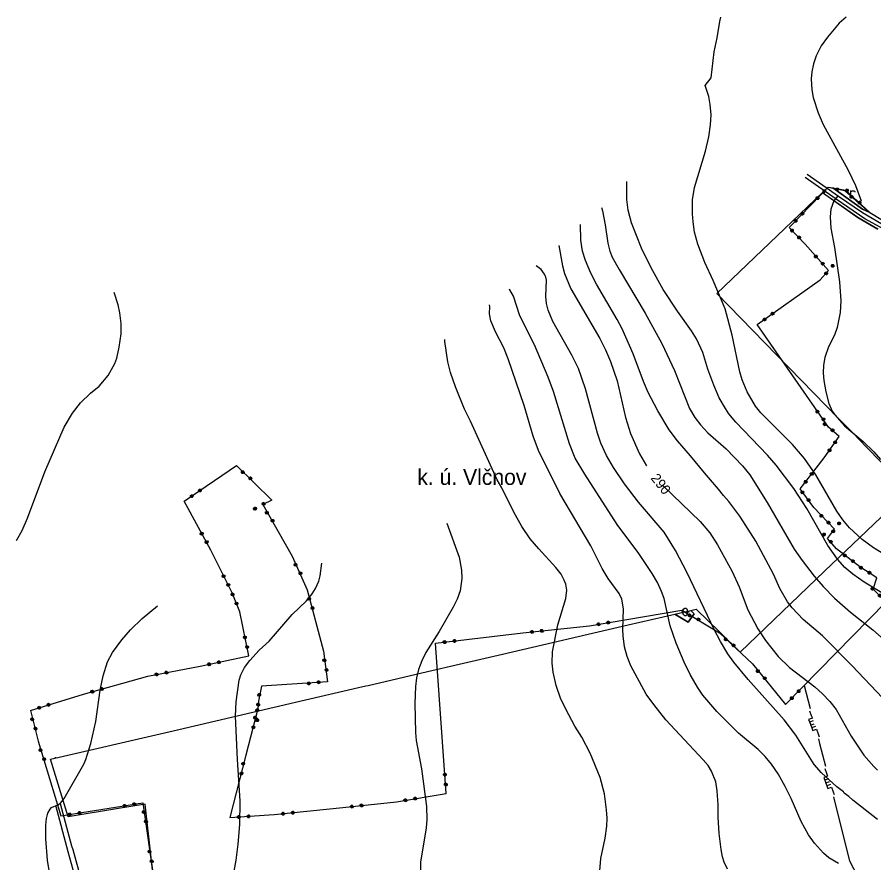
# Model space of a CAD drawing. Extents: x -645676 to -642474, y -1077513 to -1072613.
# Drawn here: x -644805 to -643720, y -1073685 to -1072613 of the extents above; entities that cross this region are included whole.
import ezdxf

# ---------------------------------------------------------------- set-up
doc = ezdxf.new("R2010")
doc.units = 0
for name, color, linetype in [('Kanalizace', 7, 'Continuous'), ('katastr_ln___zem____popis', 7, 'Continuous'), ('KULTURY_STAV', 7, 'Continuous'), ('KULTURY_ZNACKY', 7, 'Continuous'), ('PLYNOVOD', 7, 'Continuous'), ('Silnice_II__t__dy_a_III__t__dy', 7, 'Continuous'), ('SPRAV_HR_STAV', 7, 'Continuous'), ('VRSTEVNICE', 7, 'Continuous'), ('Vrstevnice_zd_razn_n____popis', 7, 'Continuous')]:
    doc.layers.add(name, color=color, linetype=linetype)

# ---------------------------------------------------------------- blocks, each defined once
blk = doc.blocks.new('3$1600')
for points in [[(-1, 1), (0.27, 1), (1, 1)], [(-0.5, 1.5), (-0.4, 1.79), (-0.15, 1.97), (0.16, 1.97), (0.41, 1.79), (0.51, 1.5), (0.51, 0.5), (0.41, 0.21), (0.16, 0.03), (-0.15, 0.03), (-0.4, 0.21), (-0.5, 0.5), (-0.5, 1.5)]]:
    blk.add_lwpolyline(points)
blk = doc.blocks.new('$479')
for points in [[(0, 0), (0, 1.27), (0, 2)], [(0, 1.6), (0.1, 1.73), (0.23, 1.84), (0.37, 1.89), (0.6, 1.9), (0.77, 1.87), (0.87, 1.8), (0.96, 1.7), (1, 1.6)]]:
    blk.add_lwpolyline(points)
blk = doc.blocks.new('6$3520')
for p, q in [((-0.76, 0), (-0.76, -1)), ((0, -1), (0, 0)), ((0.76, 0), (0.76, -1))]:
    blk.add_line(p, q)
blk.add_lwpolyline([(-3.5, 0), (-2.23, 0), (-1.48, 0), (-1.48, -1), (-0.21, -1), (1.06, -1), (1.5, -1), (1.5, 0), (2.77, 0), (3.5, 0)])
blk = doc.blocks.new('2$0620')
for points in [[(-1.07, 0.32), (-0.88, 0.13), (-0.88, -0.14), (-1.07, -0.33), (-1.34, -0.33), (-1.53, -0.14), (-1.53, 0.13), (-1.34, 0.32), (-1.07, 0.32), (-1.08, 0.28), (-1.32, 0.28), (-1.4, 0.2), (-1, 0.2), (-0.92, 0.12), (-1.48, 0.12), (-1.48, 0.04), (-0.92, 0.04), (-0.92, -0.04), (-1.48, -0.04), (-1.48, -0.12), (-0.92, -0.12), (-1, -0.2), (-1.4, -0.2), (-1.32, -0.28), (-1.08, -0.28)], [(1.43, 0.32), (1.62, 0.13), (1.62, -0.14), (1.43, -0.33), (1.16, -0.33), (0.97, -0.14), (0.97, 0.13), (1.16, 0.32), (1.43, 0.32), (1.4, 0.28), (1.16, 0.28), (1.08, 0.2), (1.48, 0.2), (1.56, 0.12), (1, 0.12), (1, 0.04), (1.56, 0.04), (1.56, -0.04), (1, -0.04), (1, -0.12), (1.56, -0.12), (1.48, -0.2), (1.08, -0.2), (1.16, -0.28), (1.4, -0.28)]]:
    blk.add_lwpolyline(points)

msp = doc.modelspace()

# ---------------------------------------------------------------- linework, layer by layer
at = {"layer": 'Kanalizace'}
msp.add_line((-644756.17, -1073551.96), (-644756.42, -1073551.04), dxfattribs=at)
at = {"layer": 'KULTURY_STAV'}
for points in [[(-643714.44, -1072882.17), (-643740.06, -1072867.17), (-643776.04, -1072841.86), (-643777.2, -1072841.05), (-643777.46, -1072840.86), (-643777.54, -1072840.81), (-643777.68, -1072840.71), (-643777.82, -1072840.61), (-643777.88, -1072840.57), (-643778.95, -1072839.82), (-643779.03, -1072839.76), (-643779.26, -1072839.6), (-643779.55, -1072839.39), (-643779.62, -1072839.35), (-643779.71, -1072839.28), (-643779.73, -1072839.27), (-643779.87, -1072839.17), (-643779.88, -1072839.16), (-643779.89, -1072839.15), (-643780.31, -1072838.86), (-643780.39, -1072838.8), (-643780.47, -1072838.74), (-643780.63, -1072838.63), (-643780.68, -1072838.6), (-643780.77, -1072838.54), (-643780.79, -1072838.52), (-643780.82, -1072838.5), (-643780.92, -1072838.43), (-643780.95, -1072838.41), (-643780.97, -1072838.4), (-643781.07, -1072838.32), (-643781.14, -1072838.27), (-643781.18, -1072838.25), (-643781.29, -1072838.17), (-643781.36, -1072838.12), (-643781.75, -1072837.85), (-643782.03, -1072837.65), (-643782.11, -1072837.59), (-643782.16, -1072837.56), (-643782.19, -1072837.54), (-643784.73, -1072835.75), (-643782.64, -1072833.75), (-643779.2, -1072830.47), (-643777.25, -1072828.61), (-643771.73, -1072829.64), (-643733.95, -1072856.58), (-643724.44, -1072860.76), (-643708.54, -1072870.7)], [(-643710.23, -1073177.1), (-643728.75, -1073158.08), (-643746.24, -1073140.18), (-643764.26, -1073121.7), (-643827.17, -1073057.19), (-643918.49, -1072963.57), (-643784.73, -1072835.75)], [(-643784.73, -1072835.75), (-643740.06, -1072867.17), (-643714.44, -1072882.17)], [(-643771.73, -1072829.64), (-643755.57, -1072832.64), (-643724.44, -1072860.76), (-643733.95, -1072856.58), (-643771.73, -1072829.64)], [(-644628.11, -1073738.88), (-644642.78, -1073610.27), (-644678.99, -1073616.27), (-644740.13, -1073626.4), (-644762.37, -1073553.42), (-644607.27, -1073517.36), (-644452.17, -1073481.3), (-644372.58, -1073462.83), (-644363.26, -1073460.66), (-644360.33, -1073459.98), (-644285.06, -1073442.49), (-644244.95, -1073433.17), (-644189.82, -1073420.36), (-644030.68, -1073383.37), (-643971.48, -1073369.61), (-643954.64, -1073379.72), (-643947.27, -1073369.34), (-643951.41, -1073364.95), (-643944.57, -1073363.36), (-643914.7, -1073392.62), (-643888.98, -1073417.72), (-643781.98, -1073315.48), (-643674.98, -1073213.24)], [(-643951.41, -1073364.95), (-643947.27, -1073369.34), (-643954.64, -1073379.72), (-643971.48, -1073369.61), (-643951.41, -1073364.95)]]:
    msp.add_lwpolyline(points, dxfattribs=at)
at = {"layer": 'PLYNOVOD'}
msp.add_line((-643807.86, -1073460.2), (-643800.12, -1073489.18), dxfattribs=at)
for points in [[(-643789.81, -1073527.83), (-643788.32, -1073533.4), (-643780.81, -1073562.44)], [(-643770.79, -1073601.17), (-643766.77, -1073616.71), (-643750.59, -1073682.42), (-643735.67, -1073710.53), (-643730, -1073721.22)]]:
    msp.add_lwpolyline(points, dxfattribs=at)
at = {"layer": 'Silnice_II__t__dy_a_III__t__dy'}
for p, q in [((-643767.49, -1072844.19), (-643806.43, -1072816.55)), ((-643804.05, -1072812.41), (-643764.29, -1072840.33)), ((-643730.8, -1072868.81), (-643767.49, -1072844.19)), ((-643764.29, -1072840.33), (-643733.83, -1072861.12)), ((-643733.83, -1072861.12), (-643709.46, -1072875.18)), ((-643702.09, -1072884.63), (-643730.8, -1072868.81)), ((-644735.51, -1073663.44), (-644749.96, -1073609.86)), ((-644756.32, -1073611.8), (-644740.46, -1073670.44)), ((-644733.99, -1073668.36), (-644735.51, -1073663.44)), ((-644740.46, -1073670.44), (-644729.82, -1073708.21)), ((-644722.67, -1073708.27), (-644733.99, -1073668.36))]:
    msp.add_line(p, q, dxfattribs=at)
at = {"layer": 'SPRAV_HR_STAV'}
for points in [[(-644787.87, -1073491.65), (-644720.61, -1073470.98), (-644639.33, -1073448.26), (-644572.82, -1073435.61), (-644511.24, -1073422.69), (-644522.87, -1073366.87), (-644532.33, -1073342.88), (-644559.47, -1073288.67), (-644593.07, -1073226.62), (-644526.87, -1073181.37), (-644482.08, -1073225.32), (-644493.71, -1073230.93), (-644456.24, -1073296.42), (-644437.29, -1073339.09), (-644416.62, -1073416.65), (-644411.45, -1073455.61), (-644495.43, -1073460.78), (-644499.12, -1073480.04), (-644499.97, -1073489.75), (-644515.24, -1073548.25), (-644535.48, -1073627.54), (-644479.2, -1073623.7), (-644392.38, -1073614.68), (-644324.4, -1073607.31), (-644261.14, -1073596.95), (-644274.68, -1073406.52), (-644164.1, -1073393.41), (-644079.74, -1073384.39), (-643962.61, -1073364.72), (-643915.1, -1073393.41), (-643873.33, -1073432.74), (-643831.55, -1073484.38), (-643704.39, -1073354.61), (-643720.43, -1073337.97), (-643715.68, -1073323.7), (-643737.22, -1073309.73), (-643766.92, -1073286.85), (-643778.21, -1073273.77), (-643769.3, -1073262.18), (-643795.73, -1073234.54), (-643812.96, -1073211.06), (-643782.37, -1073171.53), (-643763.36, -1073144.49), (-643777.17, -1073132.66), (-643867.37, -1073002.97), (-643787.71, -1072946.35), (-643776.91, -1072934.43), (-643806.54, -1072901.02), (-643826.71, -1072879.74), (-643798.93, -1072851.01), (-643777.25, -1072828.61), (-643756.13, -1072833.15)], [(-643756.13, -1072833.15), (-643724.44, -1072860.76), (-643708.54, -1072870.7), (-643699.3, -1072875.77), (-643692.85, -1072879.62), (-643690.38, -1072884.5), (-643688.96, -1072887.52)], [(-644787.87, -1073491.65), (-644778.16, -1073530.81), (-644749.52, -1073625.14)], [(-644749.52, -1073625.14), (-644645.51, -1073608.95), (-644638.26, -1073659.08), (-644631.47, -1073706.8), (-644625.41, -1073795.9), (-644596.24, -1073793.75), (-644533.17, -1073781.85), (-644523.99, -1073851.22), (-644641.02, -1073863.27), (-644639.16, -1073901.89), (-644658.59, -1073906.2)], [(-644749.52, -1073625.14), (-644645.51, -1073608.95), (-644638.26, -1073659.08), (-644632.05, -1073702.73)]]:
    msp.add_lwpolyline(points, dxfattribs=at)
at = {"layer": 'VRSTEVNICE'}
for points in [[(-643691.57, -1073302.88), (-643719.91, -1073285.65), (-643734.29, -1073275.11), (-643750.24, -1073260.58), (-643758.79, -1073250.19), (-643766.48, -1073239.22), (-643792.97, -1073193.08), (-643807.35, -1073172.57), (-643822.45, -1073154.62), (-643862.61, -1073114.6), (-643869.59, -1073106.2), (-643880.13, -1073088.25), (-643886.4, -1073072.87), (-643889.39, -1073062.62), (-643899.07, -1073016.47), (-643908.05, -1072983.15), (-643923.14, -1072947.26), (-643933.68, -1072924.18), (-643942.65, -1072901.11), (-643946.64, -1072885.73), (-643948.64, -1072872.91), (-643949.49, -1072862.66), (-643949.49, -1072844.71), (-643946.93, -1072829.33), (-643932.68, -1072783.19), (-643928.41, -1072765.24), (-643926.28, -1072749.86), (-643925.71, -1072737.04), (-643926.7, -1072724.22), (-643928.55, -1072713.97), (-643933.11, -1072700.01), (-643925.85, -1072690.19), (-643922, -1072657.57), (-643918.16, -1072639.63), (-643914.74, -1072619.12), (-643913.43, -1072613.42)], [(-643754.5, -1072613.42), (-643763.49, -1072621.25), (-643778.3, -1072638.63), (-643786.13, -1072649.74), (-643792.54, -1072662.56), (-643796.1, -1072672.52), (-643798.1, -1072682.64), (-643798.95, -1072691.75), (-643798.24, -1072705.71), (-643796.39, -1072715.39), (-643790.12, -1072734.76), (-643783.57, -1072749.29), (-643752.09, -1072807.4), (-643742.69, -1072826.77), (-643735.77, -1072845.97)], [(-643695.41, -1073351.3), (-643731.73, -1073329.23), (-643746.26, -1073319.26), (-643756.37, -1073310.57), (-643765.48, -1073300.18), (-643777.73, -1073282.8), (-643804.36, -1073235.8), (-643820.74, -1073210.74), (-643843.39, -1073181.11), (-643854.21, -1073168.15), (-643894.23, -1073126.71), (-643903.06, -1073116.02), (-643907.62, -1073109.33), (-643915.45, -1073095.66), (-643922.43, -1073079.71), (-643929.98, -1073059.2), (-643936.39, -1073038.41), (-643944.22, -1073020.89), (-643950.63, -1073010.63), (-643968.43, -1072985.71), (-643986.38, -1072958.37), (-644001.47, -1072931.02), (-644014.01, -1072905.95), (-644026.54, -1072874.05), (-644030.81, -1072858.1), (-644032.38, -1072844.43), (-644032.46, -1072821.64)], [(-643765.18, -1072839.72), (-643770.2, -1072846.32), (-643774.03, -1072856.68), (-643775.02, -1072866.36), (-643774.03, -1072880.89), (-643769.47, -1072905.1), (-643763.2, -1072948.68), (-643761.35, -1072972.89), (-643762.35, -1072987.42), (-643766.19, -1073006.79), (-643769.61, -1073016.47), (-643777.02, -1073031), (-643781.86, -1073044.67), (-643783.28, -1073054.36), (-643783.71, -1073064.04), (-643782.86, -1073073.73), (-643780.29, -1073088.25), (-643776.59, -1073102.78), (-643772.32, -1073112.47), (-643769.18, -1073117.31), (-643756.94, -1073131.12), (-643733.15, -1073150.92), (-643719.62, -1073164.16), (-643710.93, -1073173.71)], [(-644064.63, -1072854.55), (-644063.14, -1072858.67), (-644059.72, -1072876.62), (-644056.59, -1072899.69), (-644054.03, -1072909.94), (-644050.89, -1072917.63), (-644042.35, -1072933.01), (-644009.45, -1072988.27), (-643988.23, -1073027.01), (-643972.14, -1073061.19), (-643953.19, -1073109.05), (-643946.36, -1073120.44), (-643939.09, -1073129.84), (-643929.69, -1073139.95), (-643906.48, -1073160.46), (-643885.83, -1073181.82), (-643876.57, -1073193.36), (-643854.5, -1073228.4), (-643820.46, -1073287.36), (-643810.49, -1073301.74), (-643795.11, -1073321.4), (-643783.57, -1073334.78), (-643769.47, -1073349.6), (-643748.96, -1073367.26), (-643721.05, -1073389.47), (-643706.66, -1073402.43)], [(-643708.66, -1073475.64), (-643746.82, -1073435.05), (-643784.71, -1073397.02), (-643809.06, -1073376.66), (-643823.16, -1073361.7), (-643828.86, -1073354.3), (-643838.69, -1073337.21), (-643846.8, -1073319.26), (-643869.16, -1073277.39), (-643889.25, -1073245.49), (-643903.06, -1073226.97), (-643910.04, -1073219.56), (-643916.16, -1073211.3), (-643934.25, -1073190.8), (-643951.77, -1073169.29), (-643968.43, -1073150.06), (-643978.97, -1073136.11), (-643993.36, -1073112.18), (-644005.32, -1073088.82), (-644011.16, -1073075.15), (-644024.4, -1073040.12), (-644038.5, -1073008.21), (-644044.77, -1072996.25), (-644070.83, -1072951.81), (-644077.95, -1072937.86), (-644084.93, -1072921.91), (-644088.49, -1072909.94), (-644090.77, -1072895.98), (-644091.25, -1072876.25)], [(-644118.69, -1072902.86), (-644113.99, -1072928.46), (-644111.28, -1072938.14), (-644103.59, -1072957.51), (-644066.7, -1073020.46), (-644059.44, -1073034.99), (-644053.17, -1073049.51), (-644044.77, -1073074.3), (-644034.09, -1073120.44), (-644027.96, -1073140.95), (-644016.29, -1073166.59), (-644007.6, -1073181.97)], [(-643715.06, -1073629.74), (-643746.26, -1073605.53), (-643751.24, -1073600.69), (-643757.08, -1073596.7), (-643758.08, -1073594.85), (-643766.34, -1073588.44), (-643785.99, -1073570.92), (-643794.96, -1073560.24), (-643818.32, -1073523.21), (-643833.13, -1073503.55), (-643878.85, -1073452.71), (-643896.79, -1073430.63), (-643904.49, -1073419.81), (-643913.89, -1073404.43), (-643922, -1073389.05), (-643955.9, -1073317.27), (-643970.71, -1073289.07), (-643985.38, -1073266), (-644017.57, -1073227.68), (-644035.23, -1073204.47), (-644049.19, -1073183.96), (-644058.16, -1073168.58), (-644065.28, -1073153.2), (-644069.84, -1073140.38), (-644084.65, -1073084.26), (-644093.76, -1073058.63), (-644102.02, -1073041.54), (-644126.23, -1072998.81), (-644132.22, -1072984.57), (-644134.21, -1072976.02), (-644135.07, -1072967.48), (-644134.21, -1072946.54), (-644135.21, -1072942.7), (-644136.92, -1072938.85), (-644141.05, -1072933.16), (-644147.19, -1072928.54)], [(-643764.49, -1073685.71), (-643776.45, -1073678.45), (-643783.43, -1073672.61), (-643794.54, -1073659.93), (-643802.51, -1073649.11), (-643811.77, -1073632.3), (-643824.44, -1073603.25), (-643831.85, -1073587.87), (-643840.68, -1073572.2), (-643849.08, -1073559.81), (-643857.06, -1073549.98), (-643866.03, -1073541.01), (-643890.96, -1073520.36), (-643918.3, -1073493.01), (-643936.1, -1073472.36), (-643943.08, -1073462.11), (-643952.2, -1073446.3), (-643960.03, -1073430.35), (-643970.14, -1073406.42), (-643977.41, -1073384.49), (-643985.38, -1073350.02), (-643988.51, -1073340.91), (-643993.64, -1073329.51), (-644000.33, -1073318.12), (-644017.28, -1073293.05), (-644044.63, -1073256.31), (-644085.79, -1073192.51), (-644097.75, -1073172), (-644105.16, -1073153.77), (-644125.24, -1073087.68), (-644131.93, -1073069.45), (-644149.31, -1073028.44), (-644168.11, -1072991.98), (-644176.08, -1072966.91), (-644180.5, -1072959.08), (-644181.51, -1072958.41)], [(-644805.73, -1073276.53), (-644798.46, -1073263.72), (-644791.77, -1073248.34), (-644769.84, -1073189.37), (-644745.2, -1073132.97), (-644734.52, -1073115.03), (-644724.4, -1073102.21), (-644711.87, -1073089.68), (-644701.05, -1073080.99), (-644689.51, -1073067.6), (-644681.25, -1073052.08), (-644678.69, -1073045.24), (-644675.41, -1073031.57), (-644673.13, -1073014.48), (-644672.85, -1073001.66), (-644674.56, -1072987.99), (-644676.84, -1072977.73), (-644681.96, -1072962.07)], [(-643904.91, -1073692.83), (-643909.18, -1073683.86), (-643911.32, -1073677.02), (-643913.17, -1073667.91), (-643915.59, -1073647.4), (-643916.73, -1073626.89), (-643916.73, -1073611.22), (-643918.02, -1073593.56), (-643919.87, -1073582.17), (-643925.14, -1073568.5), (-643929.41, -1073561.66), (-643935.68, -1073554.11), (-643982.96, -1073503.7), (-643998.48, -1073484.18), (-644007.88, -1073470.94), (-644027.25, -1073435.19), (-644032.24, -1073423.23), (-644035.37, -1073411.26), (-644037.08, -1073397.31), (-644037.36, -1073389.05), (-644036.51, -1073362.84), (-644038.93, -1073350.88), (-644042.35, -1073343.76), (-644056.16, -1073324.39), (-644063.85, -1073311.71), (-644078.24, -1073283.09), (-644117.55, -1073217), (-644144.18, -1073162.31), (-644151.16, -1073144.08), (-644162.55, -1073105.34), (-644182.92, -1073046.1), (-644188.47, -1073032.42), (-644199.01, -1073011.92), (-644204.85, -1072998.24), (-644206.56, -1072989.13), (-644205.99, -1072980.01), (-644206.28, -1072977.92)], [(-644066.85, -1073694.97), (-644065.56, -1073679.3), (-644059.72, -1073653.67), (-644057.73, -1073638.28), (-644057.45, -1073628.03), (-644058.02, -1073617.78), (-644060.58, -1073597.27), (-644066.42, -1073576.76), (-644079.09, -1073545.71), (-644089.35, -1073525.77), (-644098.32, -1073511.53), (-644106.15, -1073497.29), (-644115.98, -1073477.35), (-644122.11, -1073460.26), (-644125.95, -1073443.17), (-644127.09, -1073431.77), (-644126.52, -1073417.53), (-644119.68, -1073383.06), (-644109.57, -1073349.74), (-644108.43, -1073339.48), (-644109.71, -1073331.79), (-644111.71, -1073326.67), (-644115.84, -1073318.98), (-644122.25, -1073310.43), (-644144.04, -1073286.79), (-644154.72, -1073274.25), (-644165.54, -1073258.59), (-644175.51, -1073240.64), (-644190.75, -1073209.88), (-644196.59, -1073199.63), (-644230.49, -1073125.28), (-644238.04, -1073109.9), (-644249.57, -1073081.7), (-644255.84, -1073063.76), (-644259.26, -1073050.08), (-644263.1, -1073024.45), (-644263.14, -1073021.76)], [(-643986.38, -1073207.18), (-643939.38, -1073252.18), (-643927.13, -1073266.85), (-643917.45, -1073281.95), (-643899.07, -1073315.84), (-643890.24, -1073335.21), (-643879.28, -1073364.27), (-643866.32, -1073388.48), (-643856.63, -1073403), (-643840.68, -1073423.51), (-643826.3, -1073437.19), (-643794.25, -1073461.68), (-643784.57, -1073470.65), (-643775.45, -1073480.34), (-643767.33, -1073490.45), (-643748.11, -1073524.35), (-643732.3, -1073548.56), (-643719.62, -1073562.8), (-643714.78, -1073567.36)], [(-644260.68, -1073254.32), (-644244.87, -1073297.61), (-644241.74, -1073313.85), (-644241.45, -1073324.67), (-644243.73, -1073340.34), (-644247.58, -1073350.59), (-644252.56, -1073360.85), (-644270.22, -1073391.61), (-644287.03, -1073418.1), (-644292.16, -1073428.93), (-644296.29, -1073439.75), (-644298.71, -1073450.57), (-644300.27, -1073461.4), (-644301.13, -1073483.04), (-644300.27, -1073519.5), (-644299.13, -1073529.76), (-644292.73, -1073565.65), (-644286.32, -1073613.5), (-644285.75, -1073629.74), (-644286.6, -1073640.56), (-644294.01, -1073683.86), (-644293.86, -1073694.68)], [(-644537.26, -1073733.99), (-644527.29, -1073681.58), (-644524.73, -1073661.07), (-644522.74, -1073636), (-644522.17, -1073606.38), (-644525.87, -1073553.69), (-644528.15, -1073499), (-644527.29, -1073480.77), (-644523.73, -1073453.42), (-644521.6, -1073446.59), (-644516.75, -1073437.47), (-644510.06, -1073428.36), (-644498.1, -1073415.54), (-644485.42, -1073403.86), (-644456.37, -1073369.96), (-644438.14, -1073353.01), (-644431.02, -1073344.04), (-644426.89, -1073337.21), (-644422.61, -1073328.09), (-644420.76, -1073321.25), (-644418.63, -1073305.3)], [(-644764, -1073696.96), (-644766.42, -1073681.58), (-644768.56, -1073654.24), (-644768.41, -1073637.15), (-644767.42, -1073628.6), (-644765.85, -1073621.76), (-644763.14, -1073616.64), (-644761.43, -1073614.78), (-644753.17, -1073611.37), (-644749.76, -1073609.09), (-644745.2, -1073603.25), (-644720.27, -1073559.67), (-644717.71, -1073553.69), (-644711.44, -1073533.75), (-644705.18, -1073505.83), (-644699.48, -1073465.95), (-644695.92, -1073448.01), (-644690.22, -1073430.06), (-644683.96, -1073418.1), (-644672.28, -1073402.15), (-644661.03, -1073389.76), (-644646.22, -1073375.37), (-644626.85, -1073359.28)]]:
    msp.add_lwpolyline(points, dxfattribs=at)

# ---------------------------------------------------------------- block references
at = {"layer": 'KULTURY_ZNACKY', "xscale": 5, "yscale": 5}
for name, p in [('$479', (-643748.61, -1072842.95)), ('3$1600', (-643958.41, -1073371.84))]:
    msp.add_blockref(name, p, dxfattribs=at)
at = {"layer": 'PLYNOVOD', "xscale": 4.999999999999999}
for p, yscale, rotation in [((-643794.96, -1073508.5), 5.000000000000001, -70.08318800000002), ((-643775.8, -1073581.81), 4.999999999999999, -70.53153600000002)]:
    msp.add_blockref('6$3520', p, dxfattribs=dict(at, yscale=yscale, rotation=rotation))
at = {"layer": 'SPRAV_HR_STAV'}
for p, xscale, yscale, rotation in [((-643786.76, -1072838.44), 5, 4.999999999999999, 46.73868299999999), ((-643760.14, -1072832.29), 5.000000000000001, 5, -6.072057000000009), ((-643742.94, -1072844.65), 5, 4.999999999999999, -35.491612), ((-643814.55, -1072867.16), 4.999999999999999, 5.000000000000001, 46.76441700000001), ((-643818.57, -1072888.32), 5, 5, 135.799933), ((-643788.52, -1072921.34), 5, 5, 133.85606099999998), ((-643775.96, -1072933.38), 5, 5, 48.667807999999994), ((-643853.11, -1072992.83), 5, 5, 36.018552), ((-643787.16, -1073118.29), 5, 5, 126.99871399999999), ((-643776.65, -1073133.1), 5, 5, 141.855319), ((-643772.3, -1073157.21), 5.000000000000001, 5, 55.854213), ((-644514.38, -1073193.63), 5, 5, -38.95241299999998), ((-643802.25, -1073197.22), 4.999999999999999, 5, 53.17265199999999), ((-644578.62, -1073216.74), 5, 4.999999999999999, 34.952983), ((-643806.09, -1073220.43), 5, 5, 128.472445), ((-644497.84, -1073232.92), 5, 5, -150.688121), ((-644485.02, -1073246.12), 5, 5, -54.995710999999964), ((-643781.39, -1073249.53), 5, 5, 136.059562), ((-643767.54, -1073259.9), 5, 5, 53.362798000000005), ((-644567.8, -1073273.28), 5, 5, 120.497038), ((-643778.35, -1073273.6), 4.999999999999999, 5.000000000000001, 133.078729), ((-643751.08, -1073299.05), 5, 4.999999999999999, 144.873234), ((-644449.13, -1073312.42), 5.000000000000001, 5, -60.91932200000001), ((-643730.36, -1073314.18), 4.999999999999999, 5, 149.599242), ((-644540.16, -1073327.23), 5.000000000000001, 4.999999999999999, 118.63518300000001), ((-643716.54, -1073342.01), 5, 5, 136.27901), ((-644529.29, -1073350.59), 4.999999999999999, 4.999999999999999, 113.45757499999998), ((-644432.78, -1073355.99), 5, 5.000000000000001, -70.103508), ((-643947.63, -1073373.77), 5, 5, -25.382962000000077), ((-644062.48, -1073381.49), 5, 5, 9.698965), ((-644146.7, -1073391.55), 5, 5.000000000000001, 6.205696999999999), ((-644514.81, -1073405.55), 5, 5.000000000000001, 103.55052599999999), ((-644257.3, -1073404.46), 5, 4.999999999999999, 6.881051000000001), ((-643902.36, -1073405.4), 5, 4.999999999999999, -37.75339100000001), ((-644555.7, -1073432.02), 5, 5.000000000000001, 12.061802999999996), ((-644414.31, -1073434), 5, 5, -77.598462), ((-644622.13, -1073444.99), 5, 5.000000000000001, 10.959105), ((-643862.32, -1073446.35), 5, 5, -45.631452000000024), ((-644428.91, -1073456.68), 5, 5, -173.27349900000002), ((-644703.75, -1073466.27), 5, 5, 15.888676), ((-643819.3, -1073471.88), 5, 5, 46.375998), ((-644498.72, -1073477.96), 5, 5.000000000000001, -96.31811299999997), ((-644771.14, -1073486.51), 5, 4.999999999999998, 17.380823), ((-644500.64, -1073497.47), 5.000000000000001, 5, -90.36092100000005), ((-644783.66, -1073508.64), 5, 5, -71.12835000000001), ((-644504.39, -1073506.68), 5.000000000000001, 4.999999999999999, -100.17633499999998), ((-644773.08, -1073547.55), 5, 5, -68.10333200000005), ((-644519.57, -1073565.21), 5, 5, -99.85858100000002), ((-644262.38, -1073579.49), 5, 4.999999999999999, 95.70788), ((-644662.81, -1073611.64), 5, 5, 9.004962), ((-644374.98, -1073612.8), 5.000000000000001, 5.000000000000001, 6.299465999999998), ((-644307.13, -1073604.48), 5, 5.000000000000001, 9.463601), ((-644732.23, -1073622.45), 5, 5, 9.004962), ((-644732.23, -1073622.45), 5, 5, 9.004962), ((-644643.01, -1073626.27), 5, 5, -76.90624700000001), ((-644643.01, -1073626.27), 5, 5, -76.90624700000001), ((-644461.8, -1073621.89), 5, 5.000000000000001, 6.031351), ((-644518.02, -1073626.35), 4.999999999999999, 5, 3.9774979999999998), ((-644635.79, -1073676.41), 5, 5, -77.05340700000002), ((-644635.79, -1073676.41), 5, 5, -77.05340700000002)]:
    msp.add_blockref('2$0620', p, dxfattribs=dict(at, xscale=xscale, yscale=yscale, rotation=rotation))

# ---------------------------------------------------------------- texts
at = {"layer": 'katastr_ln___zem____popis'}
msp.add_text('k. ú. Vlčnov', height=20, dxfattribs=at).set_placement((-644297.93, -1073206))
at = {"layer": 'Vrstevnice_zd_razn_n____popis'}
msp.add_text('290', height=12.5, rotation=308.434, dxfattribs=at).set_placement((-644002.89, -1073197.7))

doc.saveas('drawing.dxf')
